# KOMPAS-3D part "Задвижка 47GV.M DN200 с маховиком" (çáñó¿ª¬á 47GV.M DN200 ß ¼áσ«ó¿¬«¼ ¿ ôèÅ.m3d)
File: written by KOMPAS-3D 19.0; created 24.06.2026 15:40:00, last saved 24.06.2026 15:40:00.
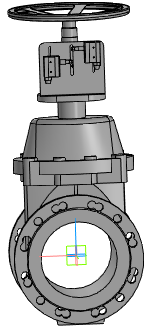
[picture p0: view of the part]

Document properties: Автор: Энергия; Полное имя файла: Z:\3.Личные\sachek\Dendor\3D для проектировщиков\2.7 Тип 47GV.M Задвижка клиновая фланцевая с обрезиненным клином\47GV.M DN200\Задвижка 47GV.M DN200 с маховиком.a3d

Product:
- Part/product: Задвижка 47GV.M DN200 с маховиком
    Масса: 93.2764
    source file: ..\47GV.M DN200\DR.47GVM.200.16.00.00 - Задвижка с обрезиненным клином DN200.spw
  - Component: Задвижка с обрезиненным клином DN200. Сборочный чертеж  | designation DR.47GVM.200.16.00.00СБ  | pos. 0  | Масса: 49.2062; Раздел спецификации: Документация; Форматы листов документа: 2xA3; source file: ..\47GV.M DN200\DR.47GVM.200.16.00.000 СБ - Задвижка с обрезиненным клином DN200.cdw
- Part/product: Задвижка 47GV.M DN200 с маховиком  | designation 01
    Масса: 49.1505
  - Component [standard]: Кольцо A50.50 ХГА ГОСТ 13943-86  | pos. 48  | Материал: Сталь 50 ХГА ГОСТ 14959-2016 (density 1000 kg/m3); Масса: 0.0068; Раздел спецификации: Стандартные изделия; Рассекать на разрезах: no
  - Component [standard]: Болт106g207798  | pos. 12  | Масса: 0.02379; Раздел спецификации: Стандартные изделия; Рассекать на разрезах: no; additional columns: ГОСТ 7798-70; М10-6gx20
  - Component [standard]: Шайба1021695878  | pos. 22  | Материал: Сталь 12Х18Н10Т ГОСТ 5632-2014 (density 1000 kg/m3); Масса: 0.0121728; Раздел спецификации: Стандартные изделия; Рассекать на разрезах: no; additional columns: ГОСТ 6958-78; A 10.21
  - Component [detail]: Маховик 320  | pos. 21  | Масса: 0.821203; Раздел спецификации: Прочие изделия; source file: ..\47GV.M DN200\Маховик 320.m3d
  - Component [assembly]: Клин с направляющими  | designation DR.47GVM.200.16.01.000  | pos. 2  | Раздел спецификации: Сборочные единицы; Форматы листов документа: A4; source file: ..\47GV.M DN200\DR.47GVM.200.16.01.000 - Клин с направляющими.a3d, ..\47GV.M DN200\DR.47GVM.200.16.01.000 - Клин с направляющими.spw, ..\47GV.M DN200\DR.47GVM.200.16.01.000 СБ - Клин с направляющими.cdw
  - Component [detail]: Шпиндель  | pos. 5  | Материал: Сталь 20Х13 ГОСТ 5632 - 2014 (density 7670 kg/m3); Масса: 0.28302; Раздел спецификации: Детали; Форматы листов документа: A3; source file: ..\47GV.M DN200\DR.47GVM.200.16.00.003 - Шпиндель.cdw, ..\47GV.M DN200\Шпиндель DN200.m3d
  - Component [detail]: Крышка DN200  | pos. 4  | Материал: ВЧ50 ГОСТ 7293-85 (density 7200 kg/m3); Масса: 27.3638; Раздел спецификации: Детали; Форматы листов документа: 2xA3; source file: ..\47GV.M DN200\DR.47GVM.200.16.00.002 - Крышка.cdw, ..\47GV.M DN200\Крышка DN200.m3d
  - Component [detail]: Корпус DN200  | pos. 3  | Материал: ВЧ50 ГОСТ 7293-85 (density 7200 kg/m3); Масса: 61.6368; Раздел спецификации: Детали; Форматы листов документа: 3xA3; source file: ..\47GV.M DN200\DR.47GVM.200.16.00.001 - Корпус.cdw, ..\47GV.M DN200\Корпус DN200.m3d
  - Component: Насадка для УКП  | designation DR.47GVM.UKP.200.16.00.001  | Материал: Сталь 08Х18Н10 ГОСТ 5632-2014 (density 7900 kg/m3); Масса: 1.37742; source file: ..\47GV.M DN200\DR.47GVM.UKP.200.16.00.001 Насадка для УКП.m3d
  - Component: Кронштейн  | designation DR.47GVM.UKP.300.16.00.002  | Материал: Ст3сп ГОСТ 380-2005 (density 7850 kg/m3); Масса: 0.323414; Раздел спецификации: Детали; Форматы листов документа: A3; source file: ..\47GV.M DN300\DR.47GVM.UKP.300.16.00.002 - Кронштейн.cdw, ..\47GV.M DN300\DR.47GVM.UKP.300.16.00.002 - Кронштейн.m3d
  - Component: Контргайка  | designation DR.47GVM.UKP.300.16.00.003  | Материал: Сталь 08Х18Н10 ГОСТ 5632-2014 (density 7900 kg/m3); Масса: 0.118067; Раздел спецификации: Детали; Форматы листов документа: A4; source file: ..\47GV.M DN300\DR.47GVM.UKP.300.16.00.003 - Контргайка.cdw, ..\47GV.M DN300\DR.47GVM.UKP.300.16.00.003 - Контргайка.m3d
  - Component: Винт установочный М6х55  | designation DR.47GVM.UKP.300.16.00.005  | Материал: Сталь 08Х18Н10 ГОСТ 5632-2014 (density 7900 kg/m3); Масса: 0.0121765; Раздел спецификации: Детали; Форматы листов документа: A4; source file: ..\47GV.M DN300\DR.47GVM.UKP.300.16.00.005 Винт установочный.m3d, ..\DR.47GVM.300.16.00.000\DR.47GVM.UKP.300.16.00.005 - Винт установочный М6х45.cdw
  - Component: Концевик AZ7311  | qty 2  | Масса: 0.377378; source file: ..\47GV.M DN50\Концевик AZ7311.m3d

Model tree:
1. Операция без истории:1

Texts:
  Точка начала. Х
  Точка начала. Y
  Точка начала. Z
